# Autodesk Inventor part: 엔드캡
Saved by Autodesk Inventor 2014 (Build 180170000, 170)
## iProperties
Created: 2026-05
Part Number: 엔드캡
Material: 강철, 연강
Document SubType Name: Modeling
Designer: dg
Density: 7.86 g/cm^3
Appearance: 강철
Mass: 28.765 g
Surface Area: 20.7543 cm^2
Volume: 3.65966 cm^3
Author: jhkim
Creation Date: 2026-04-23
Sending System: Autodesk Inventor 2027
Preprocessor: ST-DEVELOPER v20.1
Author: dg
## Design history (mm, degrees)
node "엔드캡1"
node "솔리드1"
node "기준1"
